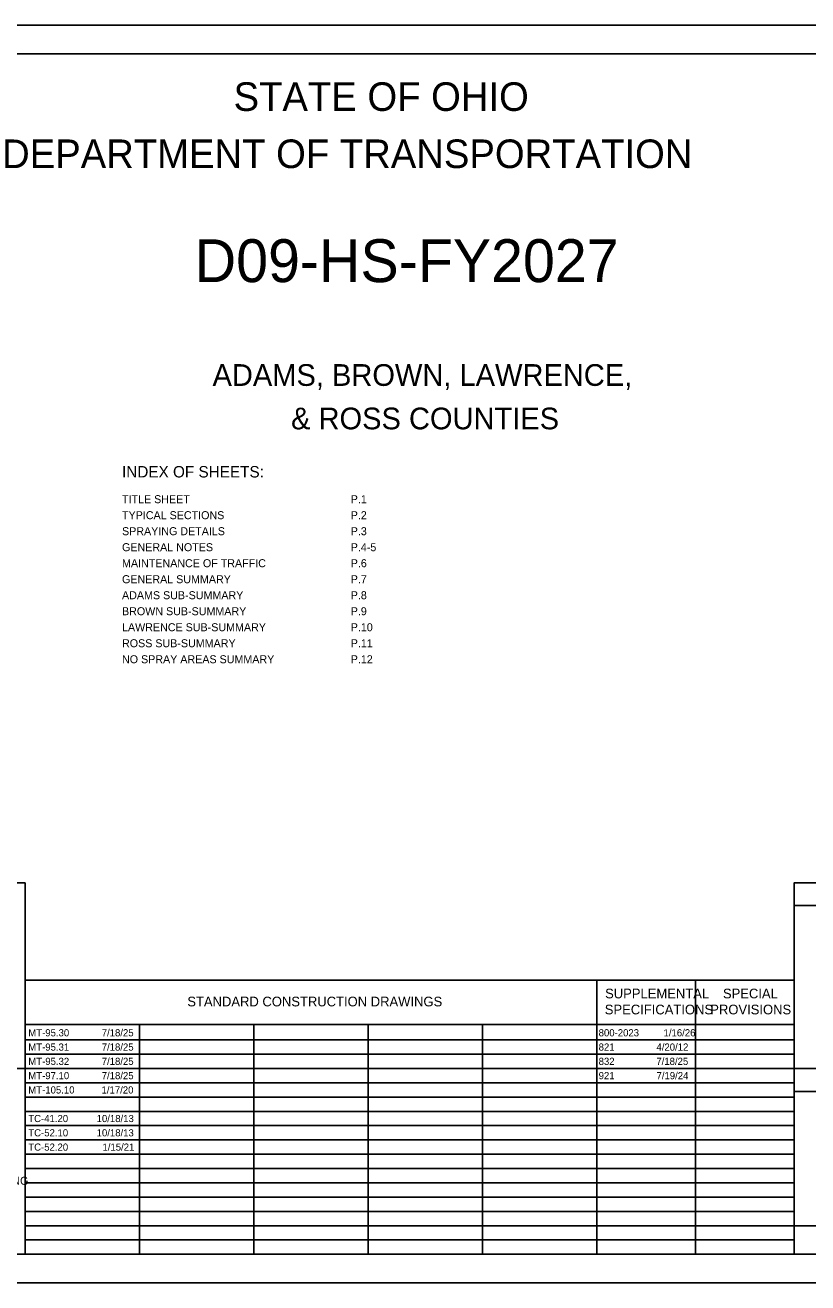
# Model space of a CAD drawing. Extents: x -6.6 to 34, y 0 to 22.
# Drawn here: x 10.15 to 23.84, y 0 to 22 of the extents above; entities that cross this region are included whole.
import ezdxf

# ---------------------------------------------------------------- set-up
doc = ezdxf.new("R2010")
doc.units = 0
for name, color, linetype in [('Default', 7, 'Continuous'), ('SH_Border', 7, 'Continuous'), ('SH_Cut_Line', 7, 'Continuous'), ('SH_Data', 7, 'Continuous'), ('SH_Text', 7, 'Continuous')]:
    doc.layers.add(name, color=color, linetype=linetype)

msp = doc.modelspace()

# ---------------------------------------------------------------- linework, layer by layer
at = {"layer": 'SH_Border'}
msp.add_lwpolyline([(1.5, 21.5), (33.5, 21.5), (33.5, 0.5), (1.5, 0.5)], close=True, dxfattribs=at)
at = {"layer": 'SH_Cut_Line'}
msp.add_lwpolyline([(0, 0), (34, 0), (34, 22), (0, 22)], close=True, dxfattribs=at)
at = {"layer": 'SH_Data'}
for p, q in [((23.6, 6.6), (26.4, 6.6)), ((10.15, 5.292), (23.6, 5.292)), ((10.15, 0.5), (10.15, 5.292)), ((20.15, 0.5), (20.15, 5.292)), ((21.875, 0.5), (21.875, 5.292)), ((23.6, 0.5), (23.6, 5.292)), ((10.15, 4.521), (23.6, 4.521)), ((12.15, 0.5), (12.15, 4.521)), ((14.15, 0.5), (14.15, 4.521)), ((16.15, 0.5), (16.15, 4.521)), ((18.15, 0.5), (18.15, 4.521)), ((10.15, 4.25), (23.6, 4.25)), ((10.15, 4), (23.6, 4)), ((10.15, 3.75), (23.6, 3.75)), ((23.6, 0.5), (23.6, 3.75)), ((23.6, 3.75), (26.4, 3.75)), ((10.15, 3.5), (23.6, 3.5)), ((23.6, 3.35), (26.4, 3.35)), ((23.6, 3.35), (26.4, 3.35)), ((10.15, 3.25), (23.6, 3.25)), ((10.15, 3), (23.6, 3)), ((10.15, 2.75), (23.6, 2.75)), ((10.15, 2.5), (23.6, 2.5)), ((10.15, 2.25), (23.6, 2.25)), ((10.15, 2), (23.6, 2)), ((10.15, 1.75), (23.6, 1.75)), ((10.15, 1.5), (23.6, 1.5)), ((10.15, 1.25), (23.6, 1.25)), ((10.15, 1), (23.6, 1)), ((10.15, 0.75), (23.6, 0.75)), ((23.6, 0.5), (26.4, 0.5))]:
    msp.add_line(p, q, dxfattribs=at)
for points in [[(10.15, 7), (7.35, 7), (7.35, 3.75), (10.15, 3.75)], [(26.4, 7), (23.6, 7), (23.6, 3.75), (26.4, 3.75)], [(10.15, 3.75), (7.35, 3.75), (7.35, 0.5), (10.15, 0.5)], [(26.4, 3.75), (23.6, 3.75), (23.6, 0.5), (26.4, 0.5)], [(23.6, 0.5), (23.6, 1), (26.4, 1), (26.4, 0.5)]]:
    msp.add_lwpolyline(points, close=True, dxfattribs=at)

# ---------------------------------------------------------------- texts
at = {"layer": 'Default'}
for s, p in [('MT-95.30', (10.205, 4.312)), ('7/18/25', (11.489, 4.312)), ('800-2023', (20.18, 4.312)), ('1/16/26', (21.315, 4.312)), ('MT-95.31', (10.205, 4.062)), ('7/18/25', (11.489, 4.062)), ('821', (20.18, 4.062)), ('4/20/12', (21.191, 4.062)), ('MT-95.32', (10.205, 3.812)), ('7/18/25', (11.489, 3.812)), ('832', (20.18, 3.812)), ('7/18/25', (21.189, 3.812)), ('MT-97.10', (10.205, 3.562)), ('7/18/25', (11.489, 3.562)), ('921', (20.18, 3.562)), ('7/19/24', (21.192, 3.562)), ('MT-105.10', (10.205, 3.312)), ('1/17/20', (11.486, 3.312)), ('TC-41.20', (10.205, 2.812)), ('10/18/13', (11.4, 2.812)), ('TC-52.10', (10.205, 2.562)), ('10/18/13', (11.4, 2.562)), ('TC-52.20', (10.205, 2.312)), ('1/15/21', (11.502, 2.312))]:
    msp.add_text(s, height=0.125, dxfattribs=at).set_placement(p)
at = {"layer": 'SH_Text'}
for s, height, p in [('STATE OF OHIO', 0.5, (13.795, 20.5)), ('DEPARTMENT OF TRANSPORTATION', 0.5, (9.747, 19.5)), ('D09-HS-FY2027', 0.75, (13.116, 17.505)), ('ADAMS, BROWN, LAWRENCE, ', 0.38, (13.427, 15.69)), ('& ROSS COUNTIES', 0.38, (14.801, 14.93)), ('INDEX OF SHEETS:', 0.2, (11.844, 14.088)), ('TITLE SHEET', 0.14, (11.844, 13.638)), ('P.1', 0.14, (15.844, 13.638)), ('TYPICAL SECTIONS', 0.14, (11.844, 13.358)), ('P.2', 0.14, (15.844, 13.358)), ('SPRAYING DETAILS', 0.14, (11.844, 13.078)), ('P.3', 0.14, (15.844, 13.078)), ('GENERAL NOTES', 0.14, (11.844, 12.798)), ('P.4-5', 0.14, (15.844, 12.798)), ('MAINTENANCE OF TRAFFIC', 0.14, (11.844, 12.518)), ('P.6', 0.14, (15.844, 12.518)), ('GENERAL SUMMARY', 0.14, (11.844, 12.238)), ('P.7', 0.14, (15.844, 12.238)), ('ADAMS SUB-SUMMARY', 0.14, (11.844, 11.958)), ('P.8', 0.14, (15.844, 11.958)), ('BROWN SUB-SUMMARY', 0.14, (11.844, 11.678)), ('P.9', 0.14, (15.844, 11.678)), ('LAWRENCE SUB-SUMMARY', 0.14, (11.844, 11.398)), ('P.10', 0.14, (15.844, 11.398)), ('ROSS SUB-SUMMARY', 0.14, (11.844, 11.118)), ('P.11', 0.14, (15.844, 11.118)), ('NO SPRAY AREAS SUMMARY', 0.14, (11.844, 10.838)), ('P.12', 0.14, (15.844, 10.838)), ('SUPPLEMENTAL', 0.17, (20.293, 4.976)), ('SPECIAL', 0.17, (22.354, 4.976)), ('STANDARD CONSTRUCTION DRAWINGS', 0.17, (12.986, 4.836)), ('SPECIFICATIONS', 0.17, (20.287, 4.696)), ('PROVISIONS', 0.17, (22.132, 4.696)), ('DISTRICT 9 ENGINEERING', 0.14, (7.824, 1.715))]:
    msp.add_text(s, height=height, dxfattribs=at).set_placement(p)

doc.saveas('drawing.dxf')
